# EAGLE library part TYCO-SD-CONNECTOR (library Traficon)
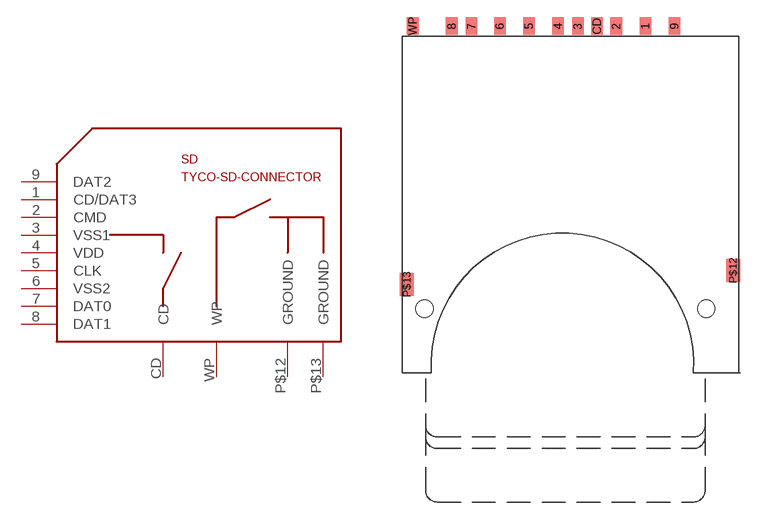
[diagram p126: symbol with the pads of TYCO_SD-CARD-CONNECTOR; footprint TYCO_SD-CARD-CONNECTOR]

Designator prefix SD

## TYCO-SD-CONNECTOR  [TYCO_SD-CARD-CONNECTOR]
1  CD/DAT3
2  CMD
3  VSS1
4  VDD
5  CLK
6  VSS2
7  DAT0
8  DAT1
9  DAT2
CD  CD
P$12  GROUND
P$13  GROUND
WP  WP

## Footprint TYCO_SD-CARD-CONNECTOR (pad centres in mm)
smd 1 x 1.5: 1 6.875,24.3; 2 4.375,24.3; 3 1.075,24.3; 4 -0.625,24.3; 5 -3.125,24.3; 6 -5.625,24.3; 7 -8.05,24.3; 8 -9.75,24.3; 9 9.375,24.3; CD 2.725,24.3; WP -13.1,24.3
smd 1.2 x 2: P$12 14.4,3.3; P$13 -13.6,2.1
hole 1.5 at -12.1,0
hole 1.5 at 12.1,0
